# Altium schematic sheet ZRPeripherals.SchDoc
size A4; PageSetup: Record=PageOptions¦CenterHorizontal=False¦CenterVertical=False¦PrintScale=1.00¦XCorrection=0.00¦YCorrection=0.00¦PrintKind=0¦BorderSize=5000000¦LeftOffset=0¦BottomOffset=0¦Orientation=2¦PaperLength=1000¦PaperWidth=1000¦Scale=100¦PaperSource=7¦PrintQuality=-3¦MediaType=1¦DitherType=10¦PrintScaleMode=1¦PaperKind=A4¦PaperIndex=9
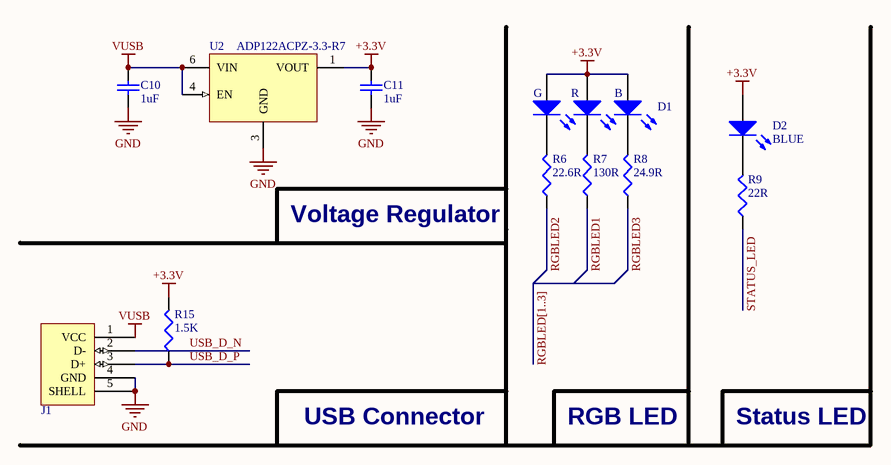
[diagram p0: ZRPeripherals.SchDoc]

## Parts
C10  1uF  [0603]
C11  1uF  [0603]
D1  SMLVN6RGB1W1  [3.5x2.8 mm 6-SMD]  (value not drawn)
D2  value BLUE  [0603 - LED]  (hidden comment: BLUE LED)
J1  48037-2200  [48037-2200]  (value not drawn)
R6  22.6R  [0402]
R7  130R  [0402]
R8  24.9R  [0402]
R9  22R  [0402]
R15  1.5K  [0402]
U2  ADP122ACPZ-3.3-R7  [LFCSP-6 2.0X2.0X0.55]

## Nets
+3.3V: C11.2 D1.1(AB) D1.2(AR) D1.3(AG) D2.1(A) R15.2 U2.1(VOUT)
GND: C10.1 C11.1 J1.4(GND) J1.5(SHELL) U2.2(NC) U2.3(GND) U2.5(NC) U2.7(THPAD)
VUSB: C10.2 J1.1(VCC) U2.4(EN) U2.6(VIN)
RGBLED1: R7.1
RGBLED2: R6.1
RGBLED3: R8.1
STATUS_LED: R9.1
USB_D_N: J1.2(D-)
USB_D_P: J1.3(D+) R15.1
NetD1_4: D1.4(KG) R6.2
NetD1_5: D1.5(KR) R7.2
NetD1_6: D1.6(KB) R8.2
NetD2_2: D2.2(K) R9.2

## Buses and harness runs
bus RGBLED[1..3]

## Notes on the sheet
- (near R6) Voltage Regulator
- USB Connector
- RGB LED
- Status LED

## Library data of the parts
C10 C11 = 1uF: 1uF 0603 X5R 10V ±10%
D1 = SMLVN6RGB1W1: ROHM SMLVN6RGB1W1 LED Tri-Color Blue/Green/Red Chip LED 6-Pin 1411 T/RLED Tri-Color Blue/Green/Red Chip LED 6-Pin 1411
D2 = BLUE LED: BRIGHT BLUE LED 20mA
J1 = 48037-2200: Molex USB 2.0 Connector Plug USB Type A
R6 = 22.6R: 22.6R 0402 1/16W ±0.05R
R7 = 130R: 130R 0402 1/16W ±0.05R
R8 = 24.9R: 24.9R 0402 1/16W ±0.05R
R9 = 22R: 22R 0402 1/16W ±1%
R15 = 1.5K: 1.5K 0402 1/16W ±1%
U2 = ADP122ACPZ-3.3-R7: Analog Devices ADP122ACPZ-3.3-R7 - 5.5 V Input, 300 mA, Low Quiescent  Current, CMOS Linear Regulator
